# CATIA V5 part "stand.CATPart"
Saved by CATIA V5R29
Part number: stand
Revision: HERHANG?
Definition: B??MEYEN
Nomenclature: stand
Source: Unknown
Bounding box of the stored display mesh (mm): x -658.284 to 658.284, y -1814.076 to -187.275, z -1108.284 to 48.284
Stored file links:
  C:\Users\제5강의실-27\Desktop\가치같이_내작업\stand.CATPart
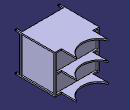
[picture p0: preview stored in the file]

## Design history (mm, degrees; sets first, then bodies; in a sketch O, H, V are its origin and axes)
Set1
  Sketch1 on face of Solid1, origin (0, 0, -1100), H (1, 0, 0), V (0, -1, 0)
    line L1 (-610, 1654.0756) -> (610, 1654.0756)
    line L2 (610, 1654.0756) -> (610, 694.0756)
    line L3 (610, 694.0756) -> (-610, 694.0756)
    line L4 (-610, 694.0756) -> (-610, 1654.0756)
    reference projected line E1 (610, 1654.0756) -> (-610, 1654.0756) from edge [face of Solid1 | face of Solid1]
    reference projected line E2 (-610, 1794.0756) -> (-610, 694.0756) from edge [face of Solid1 | face of Solid1]
    reference projected line E3 (610, 1794.0756) -> (610, 694.0756) from edge [face of Solid1 | face of Solid1]
    reference projected line E4 (-610, 694.0756) -> (610, 694.0756) from edge [face of Solid1 | face of Solid1]
    horizontal: L1 H, L3 H
    vertical: L2 V, L4 V
    coincidence: L1 E1, L4 E2, L2 E3, L3 E4
Body1 "Y?seklik-Ekstr?yon9" (main body)
  Solid1: solid without history
  Pad1: profile Sketch1, direction (0, 0, 1), length 1140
